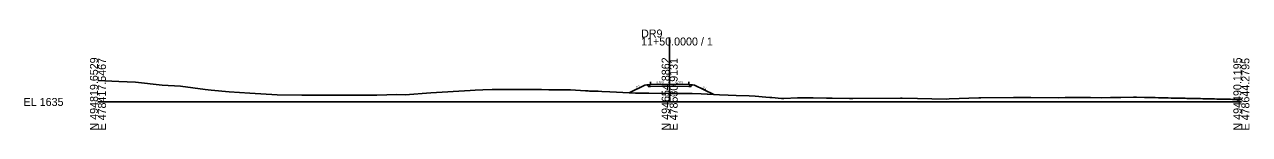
# Model space of a CAD drawing. Extents: x -26 to 403, y -10 to 1525.
# Drawn here: x -25.7 to 402.8, y 1490.3 to 1525.4 of the extents above; entities that cross this region are included whole.
import ezdxf

# ---------------------------------------------------------------- set-up
doc = ezdxf.new("R2010")
doc.units = 0
for name, color, linetype in [('Exist Cross Section Cell', 7, 'Continuous'), ('Exist XS Center Line Elevation Label', 7, 'Continuous'), ('Exist XS Ground Line', 7, 'Continuous'), ('Prop XS Dump Level', 7, 'Continuous'), ('Prop XS Earthwork Shape', 7, 'Continuous'), ('Prop XS EOT Tick Mark', 7, 'Continuous'), ('Prop XS Finish Grade', 7, 'Continuous'), ('Prop XS Finish Grade Earthwork', 7, 'Continuous'), ('Prop XS Finish Grade Pavement', 7, 'Continuous'), ('Prop XS Pvmt Edge Slope', 7, 'Continuous'), ('Prop XS SE Text', 7, 'Continuous'), ('Prop XS Shoulder Borrow Shape', 7, 'Continuous'), ('Prop XS Side Slope Text', 7, 'Continuous'), ('Prop XS Subgrade Earthwork', 7, 'Continuous'), ('Scratch_Level_5', 7, 'Continuous')]:
    doc.layers.add(name, color=color, linetype=linetype)

msp = doc.modelspace()

# ---------------------------------------------------------------- linework, layer by layer
at = {"layer": 'Exist Cross Section Cell'}
for p, q in [((200, 1500), (200, 1522.58)), ((0, 1500), (200, 1500)), ((200, 1500), (400, 1500))]:
    msp.add_line(p, q, dxfattribs=at)
at = {"layer": 'Exist XS Ground Line'}
msp.add_lwpolyline([(0, 1507.53), (7.33, 1507.12), (13.19, 1506.91), (22.42, 1505.92), (28.91, 1505.54), (37.51, 1504.34), (39.59, 1504.1), (45.92, 1503.49), (53.08, 1503.04), (62.7, 1502.54), (71.27, 1502.42), (72.94, 1502.36), (75.07, 1502.33), (78.97, 1502.37), (81.13, 1502.34), (83.74, 1502.32), (87.4, 1502.33), (89.59, 1502.37), (91.83, 1502.34), (95.27, 1502.4), (96.91, 1502.41), (97.61, 1502.4), (101.04, 1502.5), (104.36, 1502.61), (107.45, 1502.54), (116.46, 1503.15), (130.19, 1504.02), (132, 1504.16), (134.6, 1504.24), (137.89, 1504.33), (147.64, 1504.37), (150.02, 1504.4), (152.78, 1504.34), (155.16, 1504.34), (157.69, 1504.28), (163.64, 1504.26), (165.33, 1504.21), (170.57, 1503.87), (171.08, 1503.86), (171.54, 1503.85), (172, 1503.83), (175.02, 1503.72), (176.27, 1503.71), (179.09, 1503.54), (181.44, 1503.41), (188.07, 1503.09), (189.67, 1503.12), (190.3, 1503.11), (192.69, 1503.11), (200, 1502.95), (201.23, 1502.92), (203.29, 1502.92), (207.9, 1502.95), (210.99, 1502.84), (217.42, 1502.45), (220.49, 1502.38), (223.25, 1502.31), (227.85, 1502.12), (229.88, 1502.06), (233.61, 1501.62), (235.01, 1501.58), (235.69, 1501.58), (239.17, 1501.22), (239.57, 1501.21), (239.89, 1501.19), (244.77, 1501.49), (245.47, 1501.46), (249.55, 1501.45), (250.23, 1501.42), (254.86, 1501.33), (255.56, 1501.29), (256.29, 1501.27), (256.81, 1501.29), (262.88, 1501.17), (263.51, 1501.18), (264.12, 1501.19), (280.72, 1501.33), (281.03, 1501.34), (281.36, 1501.34), (286.75, 1501.23), (296.77, 1501), (297.75, 1501.06), (308.14, 1501.4), (308.88, 1501.42), (320.29, 1501.55), (321.46, 1501.56), (322.82, 1501.56), (324.42, 1501.57), (326.3, 1501.57), (336.13, 1501.49), (338.37, 1501.51), (340.93, 1501.53), (343.85, 1501.55), (347.26, 1501.57), (351.16, 1501.47), (354.19, 1501.52), (357.85, 1501.58), (362.3, 1501.65), (363.35, 1501.67), (366.16, 1501.59), (367.14, 1501.57), (368.94, 1501.53), (369.87, 1501.5), (371.06, 1501.48), (372.28, 1501.45), (374.4, 1501.4), (375.47, 1501.38), (375.78, 1501.37), (377.83, 1501.33), (378.58, 1501.31), (380.36, 1501.27), (380.88, 1501.26), (382.88, 1501.21), (383.27, 1501.2), (383.67, 1501.19), (385.68, 1501.15), (386.57, 1501.13), (387.77, 1501.1), (389.43, 1501.07), (390.62, 1501.04), (391.41, 1501.02), (391.79, 1501.01), (393.86, 1500.97), (394.6, 1500.95), (396.16, 1500.92), (396.9, 1500.9), (398.63, 1500.86), (400, 1500.83)], dxfattribs=at)
at = {"layer": 'Prop XS Dump Level'}
for p, q in [((193.28, 1506.09), (200, 1506.23)), ((200, 1506.23), (206.72, 1506.09))]:
    msp.add_line(p, q, dxfattribs=at)
at = {"layer": 'Prop XS Earthwork Shape'}
msp.add_lwpolyline([(206.72, 1505.43), (207.41, 1505.41), (207.99, 1505.99), (208.74, 1505.93), (215.47, 1502.57), (210.99, 1502.84), (207.9, 1502.95), (203.29, 1502.92), (201.23, 1502.92), (200, 1502.95), (192.69, 1503.11), (190.3, 1503.11), (189.67, 1503.12), (188.07, 1503.09), (185.8, 1503.2), (191.26, 1505.93), (192.01, 1505.99), (192.59, 1505.41), (193.28, 1505.43), (200, 1505.56)], close=True, dxfattribs=at)
at = {"layer": 'Prop XS EOT Tick Mark'}
for p, q in [((193.28, 1506.09), (193.28, 1507.09)), ((206.72, 1506.09), (206.72, 1507.09))]:
    msp.add_line(p, q, dxfattribs=at)
at = {"layer": 'Prop XS Finish Grade'}
for p, q in [((193.28, 1506.09), (192.01, 1505.99)), ((206.72, 1506.09), (207.99, 1505.99))]:
    msp.add_line(p, q, dxfattribs=at)
at = {"layer": 'Prop XS Finish Grade Earthwork'}
for p, q in [((191.26, 1505.93), (185.8, 1503.2)), ((192.01, 1505.99), (191.26, 1505.93)), ((207.99, 1505.99), (208.74, 1505.93)), ((208.74, 1505.93), (215.47, 1502.57))]:
    msp.add_line(p, q, dxfattribs=at)
at = {"layer": 'Prop XS Finish Grade Pavement'}
for p, q in [((193.28, 1506.09), (200, 1506.23)), ((200, 1506.23), (206.72, 1506.09))]:
    msp.add_line(p, q, dxfattribs=at)
at = {"layer": 'Prop XS Pvmt Edge Slope'}
for p, q in [((193.28, 1506.09), (192.59, 1505.41)), ((206.72, 1506.09), (207.41, 1505.41))]:
    msp.add_line(p, q, dxfattribs=at)
at = {"layer": 'Prop XS Shoulder Borrow Shape'}
for points in [[(193.28, 1506.09), (192.59, 1505.41), (192.01, 1505.99)], [(207.41, 1505.41), (207.99, 1505.99), (206.72, 1506.09)]]:
    msp.add_lwpolyline(points, close=True, dxfattribs=at)
at = {"layer": 'Prop XS Subgrade Earthwork'}
for p, q in [((192.59, 1505.41), (192.01, 1505.99)), ((193.28, 1505.43), (192.59, 1505.41)), ((200, 1505.56), (193.28, 1505.43)), ((206.72, 1505.43), (200, 1505.56)), ((206.72, 1505.43), (207.41, 1505.41)), ((207.41, 1505.41), (207.99, 1505.99))]:
    msp.add_line(p, q, dxfattribs=at)
at = {"layer": 'Scratch_Level_5'}
msp.add_lwpolyline([(0, 1507.53), (7.33, 1507.12), (13.19, 1506.91), (22.42, 1505.92), (28.91, 1505.54), (37.51, 1504.34), (39.59, 1504.1), (45.92, 1503.49), (53.08, 1503.04), (62.7, 1502.54), (71.27, 1502.42), (72.94, 1502.36), (75.07, 1502.33), (78.97, 1502.37), (81.13, 1502.34), (83.74, 1502.32), (87.4, 1502.33), (89.59, 1502.37), (91.83, 1502.34), (95.27, 1502.4), (96.91, 1502.41), (97.61, 1502.4), (101.04, 1502.5), (104.36, 1502.61), (107.45, 1502.54), (116.46, 1503.15), (130.19, 1504.02), (132, 1504.16), (134.6, 1504.24), (137.89, 1504.33), (147.64, 1504.37), (150.02, 1504.4), (152.78, 1504.34), (155.16, 1504.34), (157.69, 1504.28), (163.64, 1504.26), (165.33, 1504.21), (170.57, 1503.87), (171.08, 1503.86), (171.54, 1503.85), (172, 1503.83), (175.02, 1503.72), (176.27, 1503.71), (179.09, 1503.54), (181.44, 1503.41), (188.07, 1503.09), (189.67, 1503.12), (190.3, 1503.11), (192.69, 1503.11), (200, 1502.95), (201.23, 1502.92), (203.29, 1502.92), (207.9, 1502.95), (210.99, 1502.84), (217.42, 1502.45), (220.49, 1502.38), (223.25, 1502.31), (227.85, 1502.12), (229.88, 1502.06), (233.61, 1501.62), (235.01, 1501.58), (235.69, 1501.58), (239.17, 1501.22), (239.57, 1501.21), (239.89, 1501.19), (244.77, 1501.49), (245.47, 1501.46), (249.55, 1501.45), (250.23, 1501.42), (254.86, 1501.33), (255.56, 1501.29), (256.29, 1501.27), (256.81, 1501.29), (262.88, 1501.17), (263.51, 1501.18), (264.12, 1501.19), (280.72, 1501.33), (281.03, 1501.34), (281.36, 1501.34), (286.75, 1501.23), (296.77, 1501), (297.75, 1501.06), (308.14, 1501.4), (308.88, 1501.42), (320.29, 1501.55), (321.46, 1501.56), (322.82, 1501.56), (324.42, 1501.57), (326.3, 1501.57), (336.13, 1501.49), (338.37, 1501.51), (340.93, 1501.53), (343.85, 1501.55), (347.26, 1501.57), (351.16, 1501.47), (354.19, 1501.52), (357.85, 1501.58), (362.3, 1501.65), (363.35, 1501.67), (366.16, 1501.59), (367.14, 1501.57), (368.94, 1501.53), (369.87, 1501.5), (371.06, 1501.48), (372.28, 1501.45), (374.4, 1501.4), (375.47, 1501.38), (375.78, 1501.37), (377.83, 1501.33), (378.58, 1501.31), (380.36, 1501.27), (380.88, 1501.26), (382.88, 1501.21), (383.27, 1501.2), (383.67, 1501.19), (385.68, 1501.15), (386.57, 1501.13), (387.77, 1501.1), (389.43, 1501.07), (390.62, 1501.04), (391.41, 1501.02), (391.79, 1501.01), (393.86, 1500.97), (394.6, 1500.95), (396.16, 1500.92), (396.9, 1500.9), (398.63, 1500.86), (400, 1500.83)], dxfattribs=at)

# ---------------------------------------------------------------- texts
at = {"layer": 'Exist Cross Section Cell'}
for s, p in [('11+50.0000 / 1', (190, 1519.78)), ('DR9', (190, 1522.58)), ('EL 1635', (-26, 1498.6))]:
    msp.add_text(s, height=2.8, dxfattribs=at).set_placement(p)
for s, p in [('N 494819.6529', (0, 1490)), ('E 478417.5467', (2.8, 1490)), ('N 494654.8862', (200, 1490)), ('E 478530.9131', (202.8, 1490)), ('N 494490.1195', (400, 1490)), ('E 478644.2795', (402.8, 1490))]:
    msp.add_text(s, height=2.8, rotation=90, dxfattribs=at).set_placement(p)
at = {"layer": 'Exist XS Center Line Elevation Label'}
msp.add_text('1637.95', height=0.75, dxfattribs=at).set_placement((198.25, 1501.7))
at = {"layer": 'Prop XS Dump Level'}
for p in [(191.26, 1505.89), (208.74, 1505.89)]:
    msp.add_text('Case1', height=0.04, dxfattribs=at).set_placement(p)
at = {"layer": 'Prop XS SE Text'}
for rotation, p in [(1.1458, (195.35, 1506.46)), (358.8542, (202.07, 1506.51))]:
    msp.add_text('0.020', height=0.75, rotation=rotation, dxfattribs=at).set_placement(p)
at = {"layer": 'Prop XS Side Slope Text'}
for rotation, p in [(23.8531, (188.42, 1504.71)), (333.4349, (211.4, 1504.9))]:
    msp.add_text('2:1', height=0.75, rotation=rotation, dxfattribs=at).set_placement(p)

doc.saveas('drawing.dxf')
